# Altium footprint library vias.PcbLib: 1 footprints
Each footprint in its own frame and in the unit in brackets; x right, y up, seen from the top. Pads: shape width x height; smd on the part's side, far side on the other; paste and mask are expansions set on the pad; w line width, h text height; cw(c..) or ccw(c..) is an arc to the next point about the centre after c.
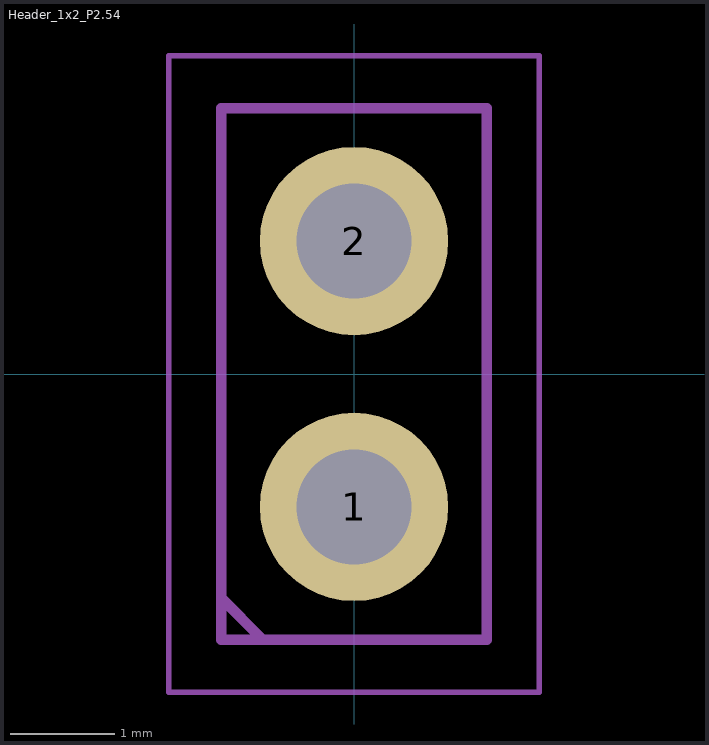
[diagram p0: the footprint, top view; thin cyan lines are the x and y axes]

## Header_1x2_P2.54 [mm] "2-position generic 2.54 mm single-row header; land pattern remains INFERRED and requires part-specific review"
pads (2):
  round 1.8 hole 1.1: 1(0,-1.27) 2(0,1.27)
Mechanical 13:
  lines w0.1: -1.27,-2.14 -0.87,-2.54 ; -1.27,-2.54 1.27,-2.54 1.27,2.54 -1.27,2.54 -1.27,-2.54
Mechanical 15:
  lines w0.05: -1.77,-3.04 1.77,-3.04 1.77,3.04 -1.77,3.04 -1.77,-3.04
